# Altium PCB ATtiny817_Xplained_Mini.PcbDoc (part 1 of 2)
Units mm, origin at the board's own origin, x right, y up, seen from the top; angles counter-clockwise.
Board outline 60 x 75 mm, 4 copper layers (Top Layer, Ground Plane, Power Plane, Bottom Layer), stack 0.778 mm thick; 64 components, 81 nets, 498 pads, 125 vias.
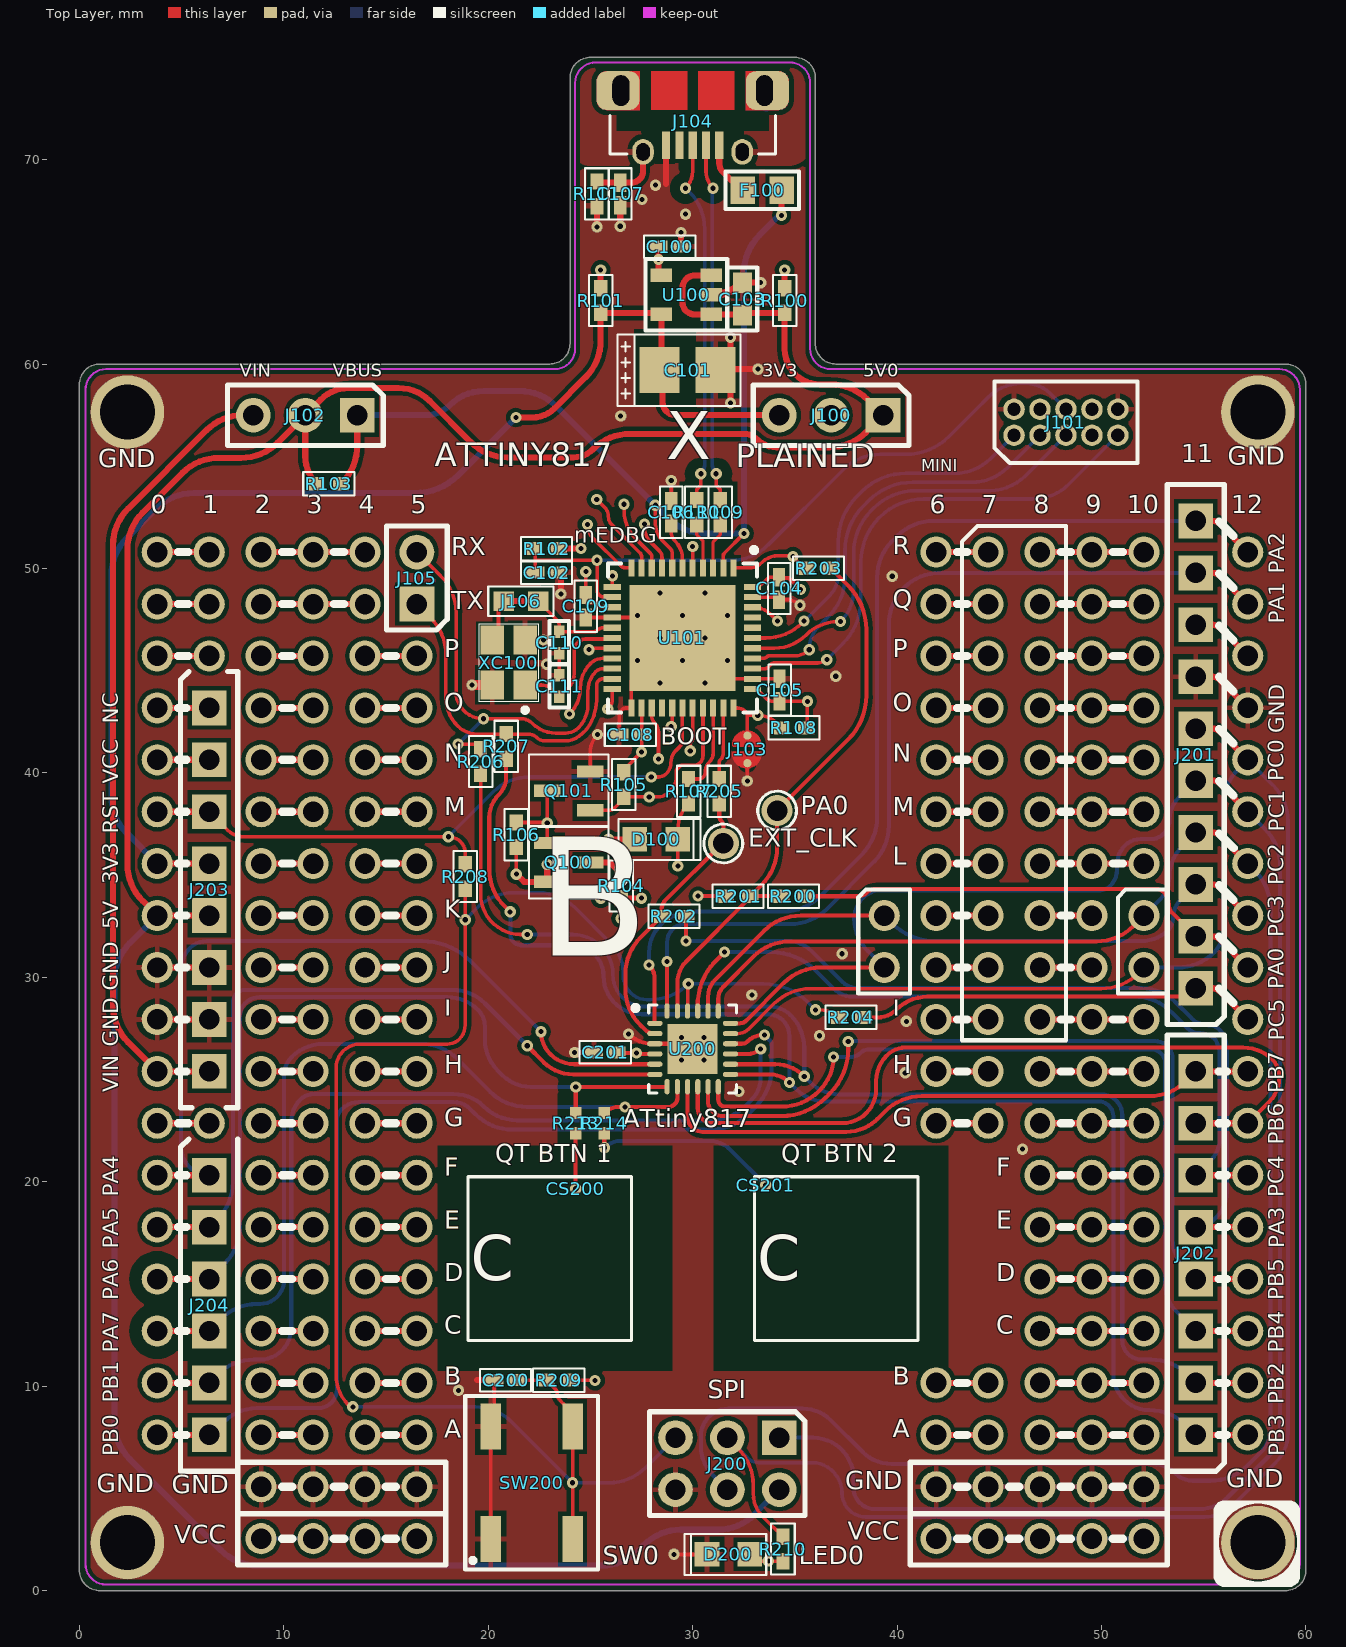
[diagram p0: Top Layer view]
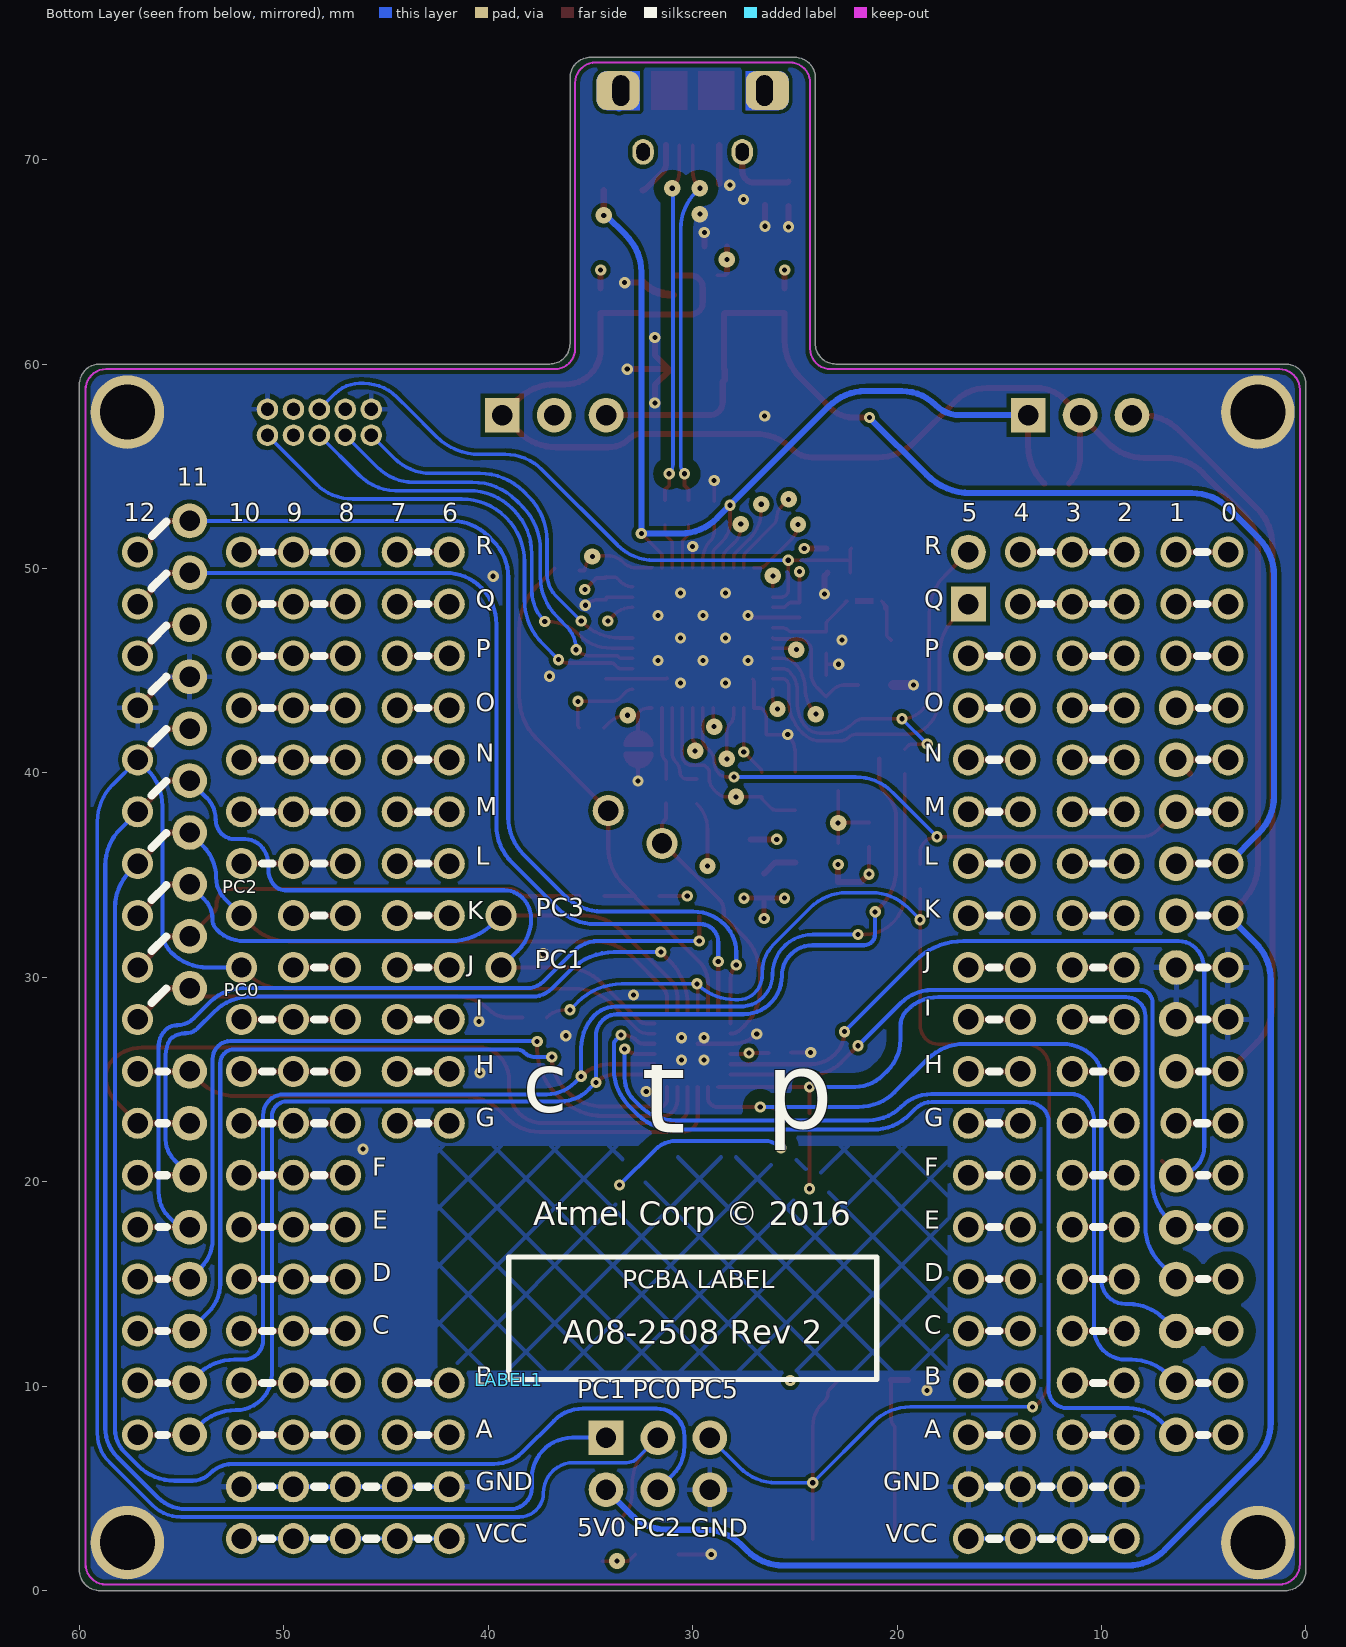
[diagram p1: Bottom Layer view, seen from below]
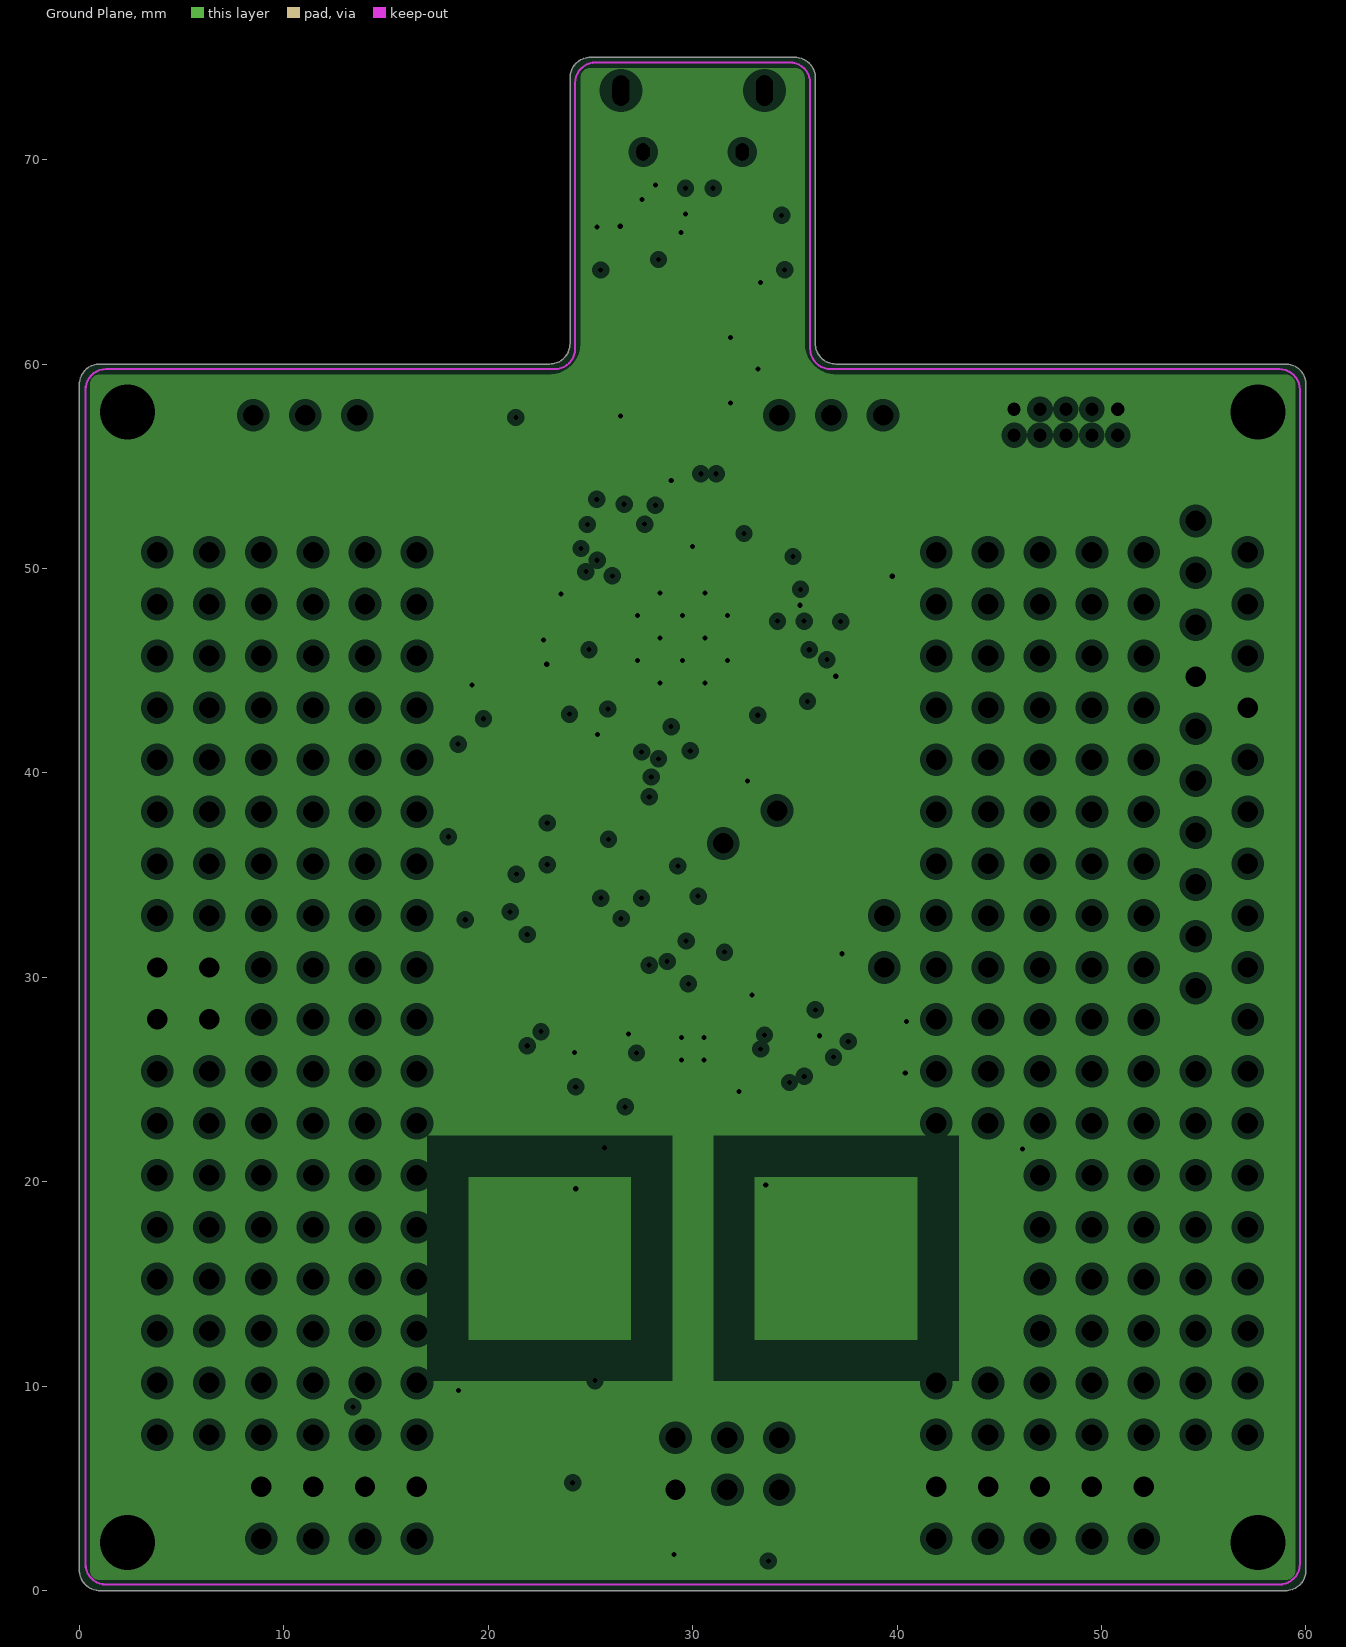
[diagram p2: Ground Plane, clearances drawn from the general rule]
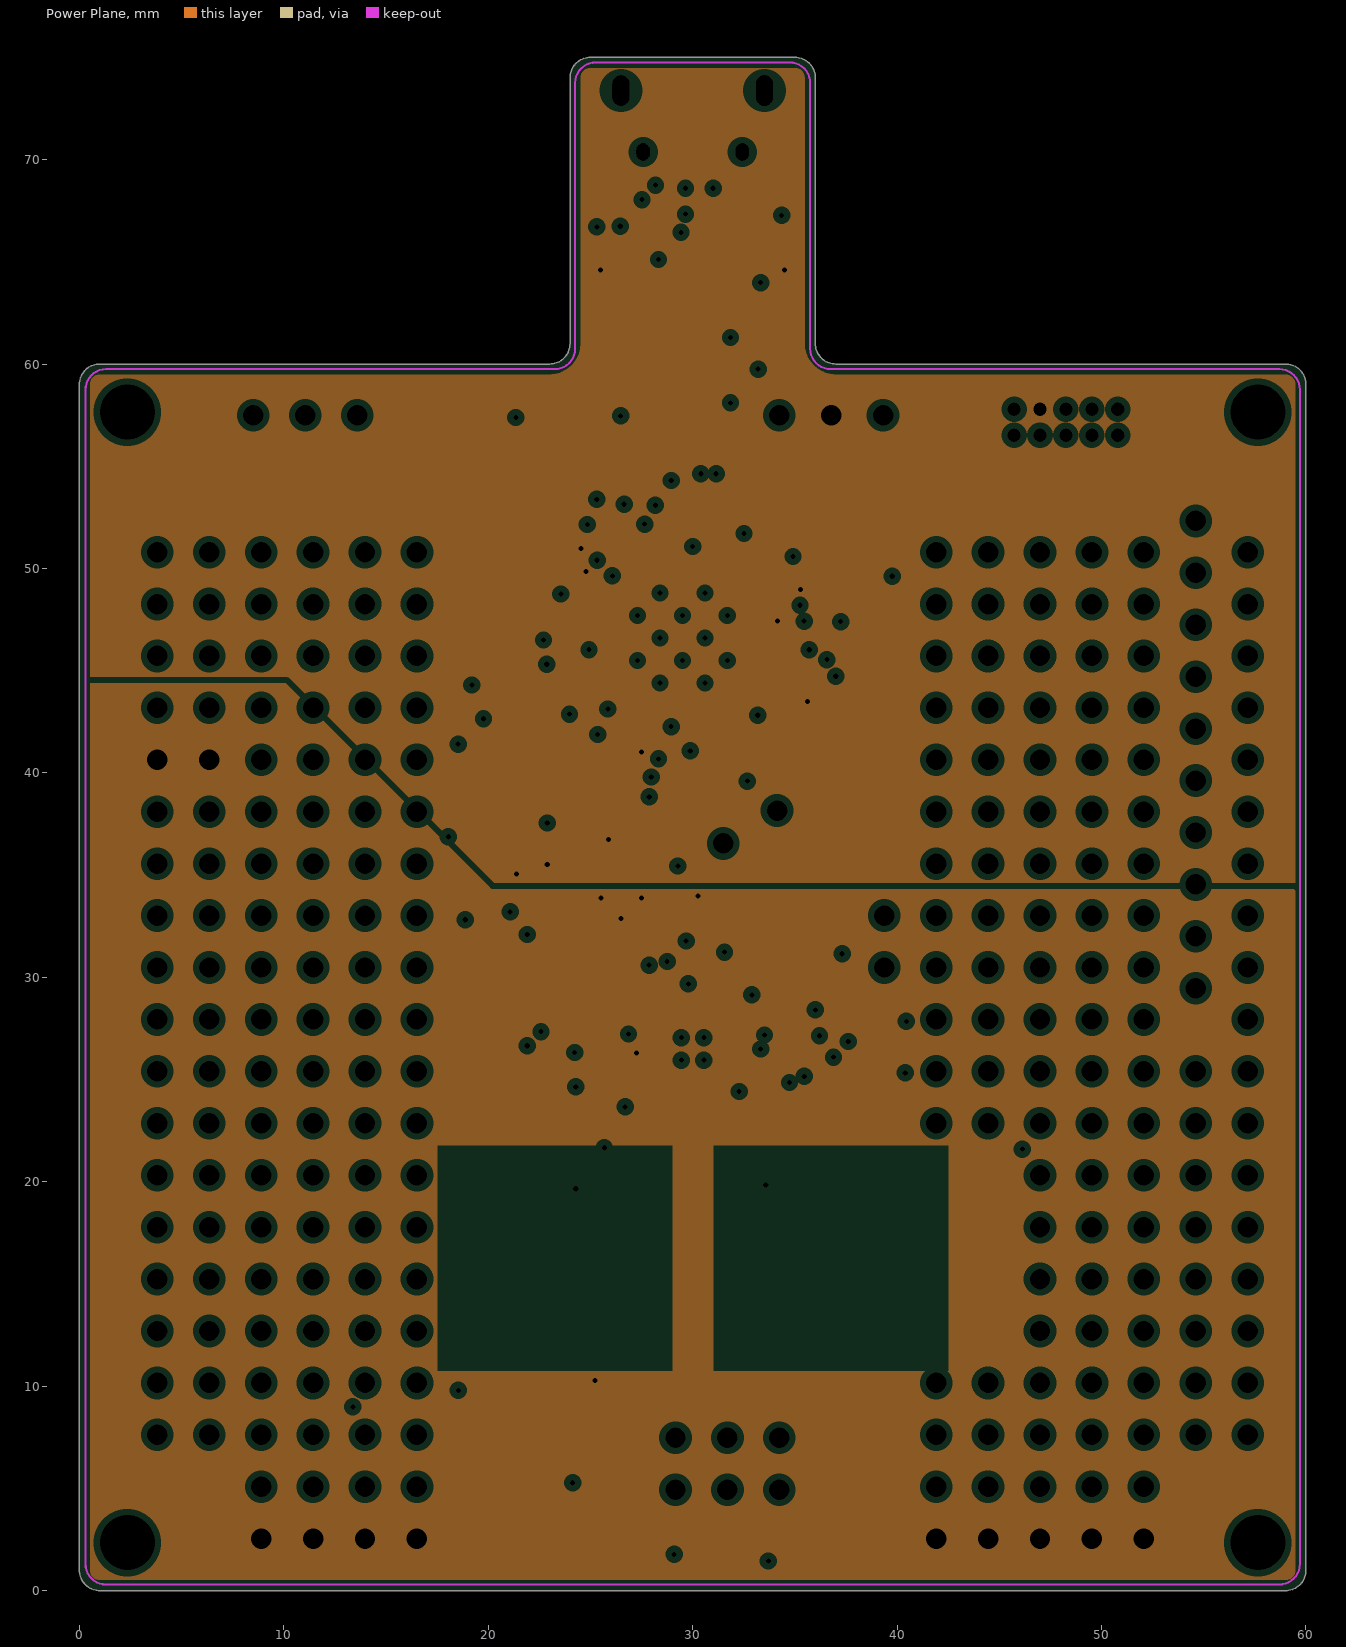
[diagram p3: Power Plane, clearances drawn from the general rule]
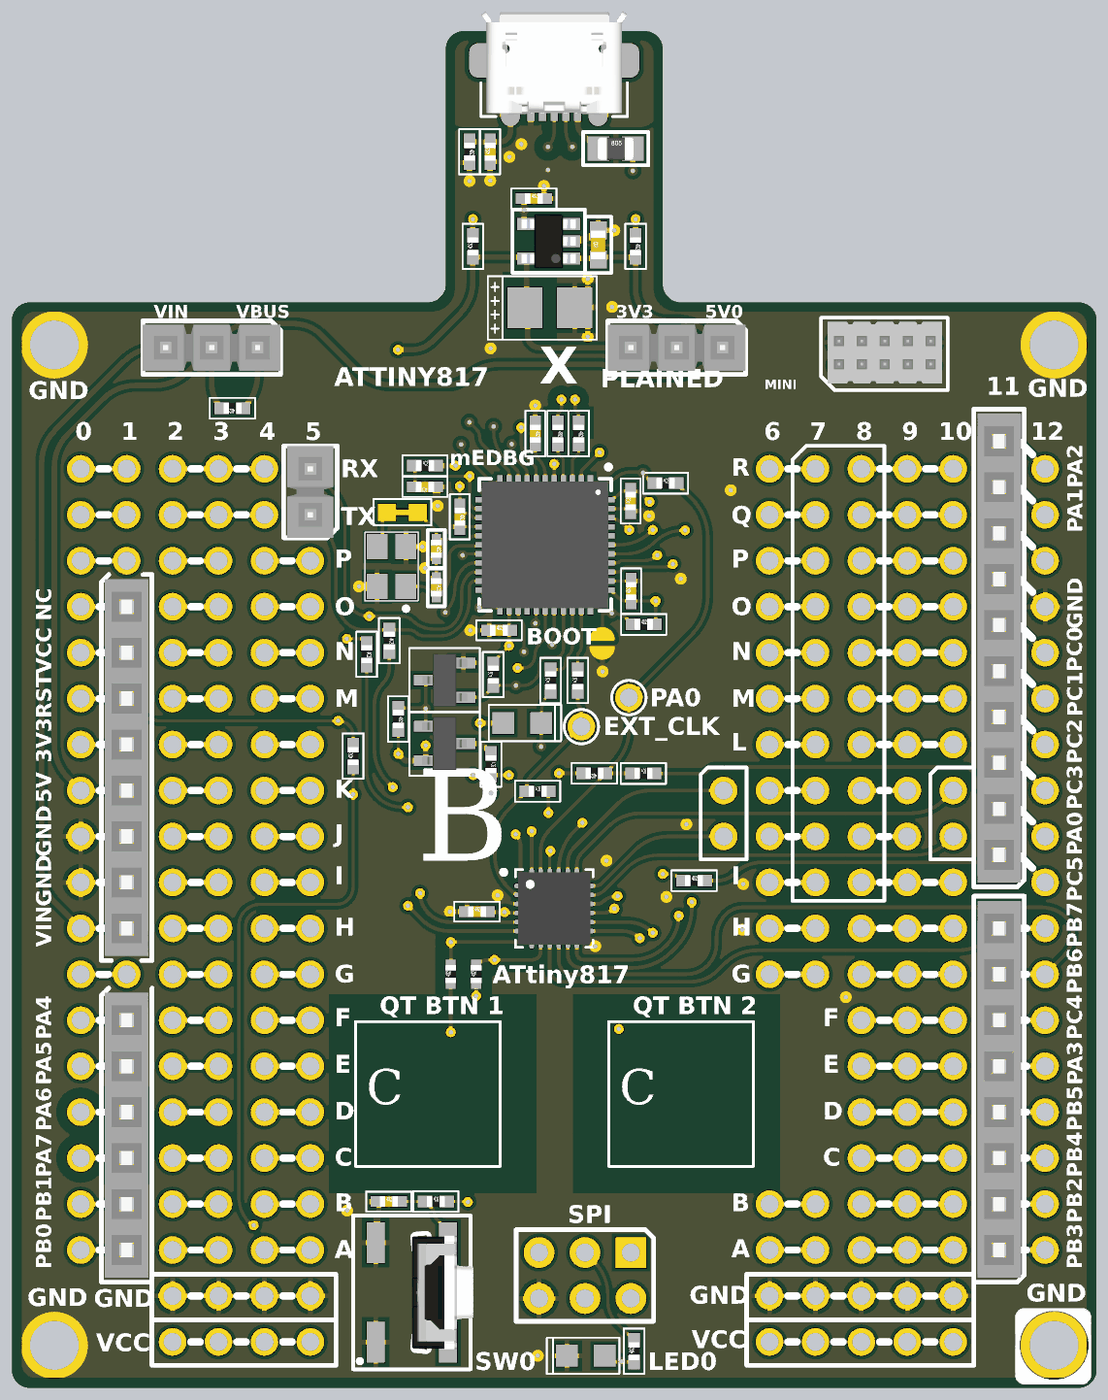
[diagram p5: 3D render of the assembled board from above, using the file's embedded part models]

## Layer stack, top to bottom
Top Solder: solder mask 0.0102, Solder Resist, Dk 3.5
Top Layer: signal copper 0.0356
Dielectric 1: core 0.254, Dk 4.2
Ground Plane: plane copper 0.036, net GND
Dielectric 4: prepreg 0.127, Dk 4.2
Power Plane: plane copper 0.0356, net (Multiple Nets)
Dielectric 3: core 0.254, Dk 4.2
Bottom Layer: signal copper 0.0356
Bottom Solder: solder mask 0.0102, Solder Resist, Dk 3.5

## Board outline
0,1 0,59 cw(c1,59) 1,60 23,60 ccw(c23,61) 24,61 24,74 cw(c25,74) 25,75 35,75 cw(c35,74) 36,74 36,61 ccw(c37,61) 37,60 59,60 cw(c59,59) 60,59 60,1 cw(c59,1) 59,0 1,0 cw(c1,1)

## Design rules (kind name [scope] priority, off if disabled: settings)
AcuteAngle [All] p1: minimum=7.50000000000000E+0001 checktracksonly=FALSE
AssemblyTestPointUsage "Schematic Assembly Testpoint Usage_21" [InNet('PA7_PTC3')] p1: valid=1
AssemblyTestPointUsage "Schematic Assembly Testpoint Usage_20" [InNet('PA6_PTC2')] p2: valid=1
AssemblyTestPointUsage "Schematic Assembly Testpoint Usage_17" [InNet('XTAL2')] p3: valid=1
AssemblyTestPointUsage "Schematic Assembly Testpoint Usage_16" [InNet('XTAL1')] p4: valid=1
AssemblyTestPointUsage "Schematic Assembly Testpoint Usage_15" [InNet('NetJ106_1')] p5: valid=1
AssemblyTestPointUsage "Schematic Assembly Testpoint Usage_1" [InNet('D_P')] p6: valid=1
AssemblyTestPointUsage "Schematic Assembly Testpoint Usage" [InNet('D_N')] p7: valid=1
AssemblyTestPointUsage [All] p8: allowmultiple=TRUE
AssemblyTestpoint [All] p1: testpointundercomponent=TRUE minsize=0.55 maxsize=2 preferedsize=0.8 minholesize=0 maxholesize=1 preferedholesize=0.25 testpointgrid=0.025 usegrid=FALSE gridtolerance=0 allowsidebottom=TRUE minspacing=1.27 compbodyclearance=0.127
Clearance Clearance_Touch [InNet('PA6_AIN06') OR InNet('PA6_PTC2') OR InNet('PA7_AIN07') OR InNet('PA7_PTC3') vs InPoly] p1: gap=0.6
Clearance Clearance_USB [InPoly vs InNet('USBD_P') OR InNet('USBD_N')] p2: gap=0.5
Clearance Clearance_Poly [InPoly] p3: gap=0.2
Clearance [All] p4: gap=0.15
DiffPairsRouting [All] p1: maxlimit=0.3 minlimit=0.15 mostfreqgap=0.2 toplayer_minwidth=0.15 toplayer_maxwidth=0.18 toplayer_prefwidth=0.15 bottomlayer_minwidth=0.15 bottomlayer_maxwidth=0.18 bottomlayer_prefwidth=0.15 maxuncoupledlength=20
FabricationTestPointUsage TestPointUsage [All] p1: valid=0 allowmultiple=TRUE
FabricationTestpoint Testpoint [All] p1: side=2 testpointundercomponent=TRUE minsize=0.55 maxsize=2 preferedsize=0.8 minholesize=0 maxholesize=1 preferedholesize=0.25 testpointgrid=0 allowsidebottom=TRUE usegrid=FALSE gridtolerance=0 minspacing=1.27 compbodyclearance=0.127
HoleSize [All] p1: absolutevalues=TRUE maxlimit=10 minlimit=0.25 maxpercent=80.000 minpercent=20.000
HoleToHoleClearance [All] p1: gap=0.45 allowstackedmicrovias=TRUE
MinimumAnnularRing MinimumAnnularRing_JTAG [InComponent('J100')] p1: minimumring=0.075
MinimumAnnularRing [All] p2: minimumring=0.15
MinimumSolderMaskSliver [All] p1: minsoldermaskwidth=0.05
NetAntennae [Not IsTestpoint] p1: netantennaetolerance=0
PlaneClearance [All] p1: clearance=0.3
PlaneConnect PlaneConnect_VIA [IsVia OR HasPad('Free-666')] p1: planeconnectstyle=Direct reliefexpansion=0.508 reliefentries=4 reliefconductorwidth=0.254 reliefairgap=0.254
PlaneConnect [All] p2: planeconnectstyle=Relief reliefexpansion=0.508 reliefentries=4 reliefconductorwidth=0.254 reliefairgap=0.254
PolygonConnect PolygonConnect_VIA [IsVia OR HasPad('Free-666')] p1: connectstyle=Direct reliefconductorwidth=0.254 reliefentries=4 polygonreliefangle="90 Angle" airgapwidth=0.254
PolygonConnect [All] p2: connectstyle=Relief reliefconductorwidth=0.254 reliefentries=4 polygonreliefangle="90 Angle" airgapwidth=0.254
RoutingVias [All] p1: holewidth=0.25 width=0.55 viastyle="Through Hole" minholewidth=0.25 minwidth=0.55 maxholewidth=0.5 maxwidth=1
SMDNeckDown [All] p1: percent=90.000
SilkToSilkClearance SilkToSilkClearance_Text [IsText] p1: silktosilkclearance=0
SilkToSilkClearance [All] p2: silktosilkclearance=0.1
SilkToSolderMaskClearance SilkscreenOverComponentPads [IsPad] p1: minsilkscreentomaskgap=0.05 clearancetoexposedcopper=TRUE
SolderMaskExpansion SolderMaskTenting [IsVia AND NOT (IsFabTestpoint OR IsAssyTestpoint)] p1: expansion=-1
SolderMaskExpansion [All] p2: expansion=0.05
ViasUnderSMD [All] p1: allowed=FALSE
Width [All] p1: maxlimit=10 minlimit=0.175 preferedwidth=0.175
17 further rules are at their usual default settings.

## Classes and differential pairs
component class ATtiny817_Xplained_Mini_TopLevel: FW1 LABEL1 PCB1 PCBADOC1 TEST2 TESTDOC1
component class "Target device": C200 C201 CS200 CS201 D200 J200 J201 J202 J203 J204 R200 R201 R202 R203 R204 R205 R206 R207 R208 R209 R210 R213 R214 SW200 U200
component class Programmer/Debug: C100 C101 C102 C103 C104 C105 C106 C107 C108 C109 C110 C111 D100 F100 J100 J101 J102 J103 J104 J105 J106 Q100 Q101 Q102 R100 R101 R102 R103 R104 R105 R106 R107 R108 R109 R110 R111 U100 U101 XC100
differential pair D: +D_P -D_N
differential pair USBD: +USBD_P -USBD_N

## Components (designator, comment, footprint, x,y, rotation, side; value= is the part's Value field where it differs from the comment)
C100 "" AP1-00001 28.88,65.746 r0 top
C101 "" AP1-00008 29.75,59.7 r0 top
C102 "" AP1-00001 22.85,49.8 r180 top
C103 "Farnell no.: 1833806" AP1-00002 32.436,63.181 r90 top
C104 "" AP1-00001 34.225,49.025 r90 top
C105 "" AP1-00001 34.25,44.05 r90 top
C106 "" AP1-00001 28.95,52.75 r270 top
C107 "" AP1-00001 26.458,68.326 r90 top
C108 "" AP1-00001 26.95,41.875 r0 top
C109 "" AP1-00001 24.775,48.15 r270 top
C110 "" AP1-00038 23.475,45.85 r180 top
C111 "" AP1-00038 23.475,43.725 r180 top
C200 "" AP1-00001 20.85,10.3 r0 top
C201 "" AP1-00001 25.725,26.325 r0 top
CS200 "QTouch Button" ?#1 23,16.2 r0 top
CS201 "QTouch Button" ?#2 37,16.2 r0 top
D100 "" AP4-00013 28.225,36.75 r180 top
D200 "" AP4-00013 31.75,1.775 r0 top
F100 "Farnell no: 1861197" AP2-00002 33.4,68.5 r0 top
J100 "" AP8-00745 36.775,57.5 r180 top locked
J101 "" AP8-00257 48.26,57.15 r0 top locked
J102 "" AP8-00745 11.05,57.5 r180 top locked
J103 "" AP9-00034 32.675,41.15 r90 top locked
J104 "2,000 pieces per reel" AP8-00851 30,73.375 r180 top locked
J105 "" AP8-00733 16.51,49.53 r90 top locked
J106 "" AP9-00044 21.6,48.4 r0 top net-tie
J200 "" AP8-00182 31.7,6.21 r180 top locked
J201 "" AP8-00822 54.61,40.894 r90 top locked
J202 "" AP8-00823#1 54.61,16.51 r90 top locked
J203 "" AP8-00823#2 6.35,34.29 r270 top locked
J204 "" AP8-00824 6.35,13.97 r270 top locked
LABEL1 "" AP8-00317 39,10.325 r180 bottom
Q100 "" AP5-00002 23.935,35.62 r0 top
Q101 "" AP5-00002 23.935,39.12 r180 top
R100 "" AP2-00000 34.5,63.1 r270 top
R101 "" AP2-00000 25.5,63.1 r90 top
R102 "" AP2-00000 22.85,50.975 r0 top
R103 "" AP2-00000 12.2,54.15 r180 top
R104 "" AP2-00000 26.502,34.473 r270 top
R105 "" AP2-00000 26.625,39.425 r90 top
R106 "" AP2-00000 21.375,36.975 r270 top
R107 "" AP2-00000 29.8,39.1 r90 top
R108 "" AP2-00000 34.95,42.2 r0 top
R109 "" AP2-00000 31.35,52.75 r270 top
R110 "" AP2-00000 30.2,52.75 r270 top
R111 "" AP2-00000 25.315,68.326 r270 top
R200 "" AP2-00000 34.929,33.964 r0 top
R201 "" AP2-00000 32.219,33.972 r180 top
R202 "" AP2-00000 29.079,32.978 r0 top
R203 "" AP2-00000 36.158,50.008 r0 top
R204 "" AP2-00000 37.738,28.036 r0 top
R205 "" AP2-00000 31.3,39.1 r90 top
R206 "" AP2-00000 19.625,40.55 r270 top
R207 "" AP2-00000 20.875,41.3 r270 top
R208 "" AP2-00000 18.875,34.925 r90 top
R209 "" AP2-00000 23.45,10.3 r0 top
R210 "" AP2-00000 34.417,2.032 r90 top
R213 "" AP2-00011 24.275,22.868 r90 top
R214 "" AP2-00011 25.675,22.868 r90 top
SW200 "" AP8-00137 22.125,5.275 r90 top
U100 "" AP6-00087 29.693,63.384 r180 top
U101 "" AP6-00375 29.5,46.6 r270 top locked
U200 "ATtiny807" AP6-00459 30,26.5 r0 top locked
XC100 "" AP7-00061 21,45.4 r90 top

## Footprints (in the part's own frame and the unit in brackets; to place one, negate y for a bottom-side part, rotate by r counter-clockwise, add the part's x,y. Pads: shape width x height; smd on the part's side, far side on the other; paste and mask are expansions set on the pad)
AP1-00001 [mm] "Standard 0402 SMD capacitor footprint"
  rect 0.9x0.6 smd: 1(-0.55,0) 2(0.55,0)
  silkscreen extent -1.25,-0.55 1.25,0.55, body extent -0.5,-0.3 0.5,0.3, height 0.2
AP1-00002 [mm]
  rect 1x0.95 smd: 1(-0.8,0) 2(0.8,0)
  silkscreen extent -1.55,-0.72 1.55,0.72, body extent -0.8,-0.4 0.8,0.4, height 0.3
AP1-00008 [mm]
  rect 1.95x2.25 smd: 1(-1.375,0) 2(1.375,0)
  silkscreen extent -3.42,-1.75 2.6,1.75, body extent -1.9,-1.5 1.9,1.5, height 2.11
AP1-00038 [mm] "Generic pad 0402, spacing 0.45mm"
  rect 0.5x0.6 smd: 1(0,0) 2(0,-1.05)
  silkscreen extent -0.48,-1.58 0.48,0.53, body extent -0.3,-1.02 0.3,-0.03, height 0.2
AP2-00000 [mm] "Standard 0402 SMD resistor footprint"
  rect 0.8x0.65 smd: 1(-0.6,0) 2(0.6,0)
  silkscreen extent -1.25,-0.58 1.25,0.58, body extent -0.5,-0.3 0.5,0.3, height 0.2
AP2-00002 [mm]
  rect 1.2x1.35 smd: 1(-0.95,0) 2(0.95,0)
  silkscreen extent -1.8,-0.92 1.8,0.92, body extent -1,-0.62 1,0.63, height 0.78
AP2-00011 [mm] "Chip Resistor, 2-Leads, Body 1,0x0,5mm, IPC High Density"
  rect 0.6x0.55 smd: 1(-0.5,0) 2(0.5,0)
  body extent -0.5,-0.3 0.5,0.3, height 0.2
AP4-00013 [mm] "0805 diode footprint"
  rect 1.2x1.2 smd: 1(-1.05,0) 2(1.05,0)
  silkscreen extent -2.16,-1 1.85,1, body extent -1,-0.63 1,0.63, height 1.1
AP5-00002 [mm] "SOT-23 Package"
  rect 1.3x0.6 smd: 1(-1.05,0.95) 2(-1.05,-0.95) 3(1.05,0)
  silkscreen extent -1.95,-1.78 1.95,1.78, body extent -1.25,-1.46 1.23,1.46, height 1
AP6-00087 [mm]
  rect 1.05x0.65 smd: 1(-1.225,0.953) 2(-1.225,0) 3(-1.225,-0.953) 4(1.225,-0.953) 5(1.225,0.953)
  silkscreen extent -2,-1.75 2,1.75, body extent -1.5,-1.5 1.5,1.5, height 1.3
AP6-00375 [mm] "QFN, 44-Leads, Body 7,00x7,00mm, Pitch 0,50mm, Thermal Pad 5,20x5,20mm, IPC Medium Density"
  rect 0.85x0.3 smd: 1(-3.425,2.5) 2(-3.425,2) 3(-3.425,1.5) 4(-3.425,1) 5(-3.425,0.5) 6(-3.425,0) 7(-3.425,-0.5) 8(-3.425,-1) 9(-3.425,-1.5) 10(-3.425,-2) 11(-3.425,-2.5) 23(3.425,-2.5) 24(3.425,-2) 25(3.425,-1.5) 26(3.425,-1) 27(3.425,-0.5) 28(3.425,0) 29(3.425,0.5) 30(3.425,1) 31(3.425,1.5) 32(3.425,2) 33(3.425,2.5)
  rect 0.3x0.85 smd: 12(-2.5,-3.425) 13(-2,-3.425) 14(-1.5,-3.425) 15(-1,-3.425) 16(-0.5,-3.425) 17(0,-3.425) 18(0.5,-3.425) 19(1,-3.425) 20(1.5,-3.425) 21(2,-3.425) 22(2.5,-3.425) 34(2.5,3.425) 35(2,3.425) 36(1.5,3.425) 37(1,3.425) 38(0.5,3.425) 39(0,3.425) 40(-0.5,3.425) 41(-1,3.425) 42(-1.5,3.425) 43(-2,3.425) 44(-2.5,3.425)
  rect 5.2x5.2 smd: 45(0,0)
  silkscreen extent -4.42,-3.65 3.65,3.65, body extent -3.5,-3.5 3.5,3.5, height 0.89
AP6-00459 [mm] "QFN, 24-Leads, Body 4,00x4,00mm, Pitch 0,50mm, Thermal Pad 2,45x2,45mm, IPC High Density"
  oval 0.75x0.25 smd: 1(-1.85,1.25) 2(-1.85,0.75) 3(-1.85,0.25) 4(-1.85,-0.25) 5(-1.85,-0.75) 6(-1.85,-1.25) 13(1.85,-1.25) 14(1.85,-0.75) 15(1.85,-0.25) 16(1.85,0.25) 17(1.85,0.75) 18(1.85,1.25)
  oval 0.25x0.75 smd: 7(-1.25,-1.85) 8(-0.75,-1.85) 9(-0.25,-1.85) 10(0.25,-1.85) 11(0.75,-1.85) 12(1.25,-1.85) 19(1.25,1.85) 20(0.75,1.85) 21(0.25,1.85) 22(-0.25,1.85) 23(-0.75,1.85) 24(-1.25,1.85)
  rect 2.45x2.45 smd: 25(0,0)
  silkscreen extent -2.92,-2.15 2.15,2.15, body extent -2,-2 2,2, height 0.9
AP7-00061 [mm] "TSX-3225"
  rect 1.4x1.15 smd: 1(-1.1,-0.8) 2(1.1,-0.8) 3(1.1,0.8) 4(-1.1,0.8)
  silkscreen extent -2.43,-1.48 1.9,1.48, body extent -1.6,-1.25 1.6,1.25, height 0.6
AP8-00137 [mm]
  rect 2.25x1 smd: 1(-2.75,2) 2(2.75,2) 3(-2.75,-2) 4(2.75,-2)
  silkscreen extent -4.25,-3.25 4.25,3.25, body extent -3.4,-3.21 3.4,3.22, height 3.47
AP8-00182 [mm] "Pin-in-Paste, Throughhole pin-header (2x3 array). Pitch 2.54 mm"
  rect 1.7x1.7 / inner round 1.7 / far side rect 1.7x1.7 hole 1: 1(-2.54,-1.27)
  rect 0x0 on Top Paste paste-2: 1(-2.54,-1.27) 2(-2.54,1.27) 3(0,-1.27) 4(0,1.27) 5(2.54,-1.27) 6(2.54,1.27)
  round 1.7 hole 1: 2(-2.54,1.27) 3(0,-1.27) 4(0,1.27) 5(2.54,-1.27) 6(2.54,1.27)
  silkscreen extent -3.8,-2.54 3.81,2.54, body extent -3.81,-2.54 3.81,2.54, height 8
AP8-00257 [mm]
  round 1.05 hole 0.65: 1(-2.54,-0.635) 2(-2.54,0.635) 3(-1.27,-0.635) 4(-1.27,0.635) 5(0,-0.635) 6(0,0.635) 7(1.27,-0.635) 8(1.27,0.635) 9(2.54,-0.635) 10(2.54,0.635)
  silkscreen extent -3.5,-2 3.5,2, body extent -3.15,-1.64 3.2,1.79, height 3.88
AP8-00317 [mm] "Placement area for 18x6mm sticker"
  silkscreen extent 0,0 18,6
AP8-00733 [mm] "Pin header 1x2 Pin in Paste"
  rect 1.7x1.7 / inner round 1.7 / far side rect 1.7x1.7 hole 1: 1(-1.27,0)
  rect 0x0 on Top Paste paste-2: 1(-1.27,0)
  round 1.7 hole 1: 2(1.27,0)
  rect 0x0 on Top Paste paste+2: 2(1.27,0)
  silkscreen extent -2.54,-1.48 2.54,1.48, body extent -2.54,-1.27 2.54,1.27, height 8.38
AP8-00745 [mm] "THM Pin-header 1x3 100mil pitch, 1mm hole"
  rect 1.7x1.7 / inner round 1.7 / far side rect 1.7x1.7 hole 1: 1(-2.54,0)
  round 1.7 hole 1: 2(0,0) 3(2.54,0)
  silkscreen extent -3.81,-1.48 3.81,1.48, body extent -3.81,-1.27 3.81,1.27, height 8.38
AP8-00822 [mm]
  rect 1.7x1.7 / inner round 1.7 / far side round 1.7 hole 1: 1(-11.43,0) 2(-8.89,0) 3(-6.35,0) 4(-3.81,0) 5(-1.27,0) 6(1.27,0) 7(3.81,0) 8(6.35,0) 9(8.89,0)
  rect 0x0 on Top Paste paste-2: 1(-11.43,0) 2(-8.89,0) 3(-6.35,0) 4(-3.81,0) 5(-1.27,0) 6(1.27,0) 7(3.81,0) 8(6.35,0) 9(8.89,0)
  rect 1.7x1.7 / inner round 1.7 / far side round 1.7 hole 1 paste+2: 10(11.43,0)
  rect 0x0 on Top Paste paste+2: 10(11.43,0)
  silkscreen extent -13.21,-1.4 13.21,1.4, body extent -12.95,-1.21 12.95,1.21, height 8.51
AP8-00823#1 [mm]
  rect 1.7x1.7 / inner round 1.7 / far side round 1.7 hole 1: 1(-8.89,0) 2(-6.35,0) 3(-3.81,0) 4(-1.27,0) 5(1.27,0) 6(3.81,0) 7(6.35,0) 8(8.89,0)
  silkscreen extent -10.67,-1.4 10.67,1.4, body extent -10.41,-1.21 10.41,1.21, height 8.51
AP8-00823#2 [mm]
  rect 1.7x1.7 / inner round 1.7 / far side round 1.7 hole 1: 1(-8.89,0) 2(-6.35,0) 3(-3.81,0) 4(-1.27,0) 5(1.27,0) 6(3.81,0) 7(6.35,0) 8(8.89,0)
  rect 0x0 on Top Paste paste-2: 1(-8.89,0) 2(-6.35,0) 3(-3.81,0) 4(-1.27,0) 5(1.27,0) 6(3.81,0) 7(6.35,0) 8(8.89,0)
  silkscreen extent -10.67,-1.4 10.67,1.4, body extent -10.41,-1.21 10.41,1.21, height 8.51
AP8-00824 [mm]
  rect 1.7x1.7 / inner round 1.7 / far side round 1.7 hole 1: 1(-6.35,0) 2(-3.81,0) 3(-1.27,0) 4(1.27,0) 5(3.81,0) 6(6.35,0)
  rect 0x0 on Top Paste paste-2: 1(-6.35,0) 2(-3.81,0) 3(-1.27,0) 4(1.27,0) 5(3.81,0) 6(6.35,0)
  silkscreen extent -8.13,-1.4 8.13,1.4, body extent -7.87,-1.21 7.87,1.21, height 8.51
AP8-00851 [mm] "Hirose, ZX Series, USB Micro-B Recept-RA"
  rect 0.4x1.35 smd: 1(-1.3,2.675) 2(-0.65,2.675) 3(0,2.675) 4(0.65,2.675) 5(1.3,2.675)
  rrect52% 2.1x1.9 on Top Paste: 6(-3.6,0) 7(3.6,0)
  rrect52% 2.1x1.9 hole 0.825 slot 1.5 at 90 deg copper offset -0.138,0: 6(-3.512,0)
  rrect52% 2.1x1.9 hole 0.825 slot 1.5 at 90 deg copper offset 0.138,0: 7(3.512,0)
  rrect100% 1.05x1.25 hole 0.65 slot 0.85 at 90 deg: 8(-2.425,3) 9(2.425,3)
  rrect100% 1.05x1.25 on Top Paste: 8(-2.425,3) 9(2.425,3)
  Top Layer region: 0.249,-0.95 2.049,-0.95 2.049,0.95 0.249,0.95
  Top Layer region: -2.049,-0.95 -0.249,-0.95 -0.249,0.95 -2.049,0.95
  Top Layer region: 2.6,-0.95 4.2,-0.95 4.294,-0.941 4.381,-0.915 4.434,-0.891 4.48,-0.862 4.52,-0.832 4.565,-0.791 4.596,-0.753 4.622,-0.716 4.647,-0.673 4.66,-0.64 4.676,-0.6 4.688,-0.55 4.696,-0.505 4.7,-0.45 4.7,0.45 4.696,0.503 4.689,0.548 4.677,0.599 4.661,0.641 4.641,0.683 4.617,0.724 4.589,0.761 4.56,0.797 4.521,0.831 4.483,0.86 4.439,0.888 4.397,0.908 4.354,0.924 4.301,0.939 4.248,0.946 4.2,0.95 2.6,0.95
  Top Layer region: -2.6,0.95 -4.2,0.95 -4.294,0.941 -4.381,0.915 -4.434,0.891 -4.48,0.862 -4.52,0.832 -4.565,0.791 -4.596,0.753 -4.622,0.716 -4.647,0.673 -4.66,0.64 -4.676,0.6 -4.688,0.55 -4.696,0.505 -4.7,0.45 -4.7,-0.45 -4.696,-0.503 -4.689,-0.548 -4.677,-0.599 -4.661,-0.641 -4.641,-0.683 -4.617,-0.724 -4.589,-0.761 -4.56,-0.797 -4.521,-0.831 -4.483,-0.86 -4.439,-0.888 -4.397,-0.908 -4.354,-0.924 -4.301,-0.939 -4.248,-0.946 -4.2,-0.95 -2.6,-0.95
  Top Layer pour cut-out: -3.75,2 3.75,2 3.75,-1.45 -3.75,-1.45
  Bottom Layer region: -2.6,0.95 -4.2,0.95 -4.294,0.941 -4.381,0.915 -4.434,0.891 -4.48,0.862 -4.52,0.832 -4.565,0.791 -4.596,0.753 -4.622,0.716 -4.647,0.673 -4.66,0.64 -4.676,0.6 -4.688,0.55 -4.696,0.505 -4.7,0.45 -4.7,-0.45 -4.696,-0.503 -4.689,-0.548 -4.677,-0.599 -4.661,-0.641 -4.641,-0.683 -4.617,-0.724 -4.589,-0.761 -4.56,-0.797 -4.521,-0.831 -4.483,-0.86 -4.439,-0.888 -4.397,-0.908 -4.354,-0.924 -4.301,-0.939 -4.248,-0.946 -4.2,-0.95 -2.6,-0.95
  Bottom Layer region: 2.6,-0.95 4.2,-0.95 4.294,-0.941 4.381,-0.915 4.434,-0.891 4.48,-0.862 4.52,-0.832 4.565,-0.791 4.596,-0.753 4.622,-0.716 4.647,-0.673 4.66,-0.64 4.676,-0.6 4.688,-0.55 4.696,-0.505 4.7,-0.45 4.7,0.45 4.696,0.503 4.689,0.548 4.677,0.599 4.661,0.641 4.641,0.683 4.617,0.724 4.589,0.761 4.56,0.797 4.521,0.831 4.483,0.86 4.439,0.888 4.397,0.908 4.354,0.924 4.301,0.939 4.248,0.946 4.2,0.95 2.6,0.95
  silkscreen extent -4.05,1.22 4.05,3.1, body extent -4.05,-2.7 4.05,3.1, height 2.75
AP9-00034 [mm] "PCB implemented strap, open"
  round 0.4 smd paste-0.4 mask-0.4: 1(-0.675,0) 2(0.675,0)
  Top Layer region: 0.2,0.675 0.482,0.611 0.708,0.43 0.834,0.17 0.834,-0.12 0.708,-0.38 0.482,-0.561 0.2,-0.625 0.2,-0.625
  Top Layer region: -0.2,-0.625 -0.482,-0.561 -0.708,-0.38 -0.834,-0.12 -0.834,0.17 -0.708,0.43 -0.482,0.611 -0.2,0.675 -0.2,0.675
  Top Layer lines w0.175: -0.2,0.675 ccw(c-0.2,0.025) -0.85,0 ccw(c-0.2,0.025) -0.2,-0.625 -0.2,0.675 ; 0.2,0.675 cw(c0.2,0.025) 0.85,0 cw(c0.2,0.025) 0.2,-0.625 0.2,0.675
AP9-00044 [mm]
  rect 1x0.95 smd paste-1: 1(-0.85,0) 2(0.85,0)
  Top Layer region: -0.45,-0.15 0.45,-0.15 0.45,0.15 -0.45,0.15
  silkscreen extent -1.6,-0.72 1.6,0.72, body extent -0.8,-0.4 0.8,0.4, height 0.3
?#1 [mm]
  round 0.55 smd paste-1 mask-1: 1(1.281,3.458)
  Ground Plane region: -5.975,-3.956 -5.975,6.042 6.012,6.042 6.012,-5.946 4.005,-5.946 -5.975,-5.946 -5.975,-3.956 4.005,-3.956 4.005,4.053 -3.986,4.053 -3.986,-3.956
?#2 [mm]
  round 0.55 smd paste-1 mask-1: 1(-3.425,3.638)
  Ground Plane region: -5.975,-3.956 -5.975,6.042 6.012,6.042 6.012,-5.946 4.005,-5.946 -5.975,-5.946 -5.975,-3.956 4.005,-3.956 4.005,4.053 -3.986,4.053 -3.986,-3.956

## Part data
C100: library part A01-0050, "Ceramic capacitor, SMD 0402, X7R, 25V, +/-10%"
C101: library part A01-0292, "SMD tantalum capacitor, precision molded chip, ESR=0,5"
C102 C104 C105 C108 C109 C200 C201: library part A01-0246, "Ceramic capacitor, SMD 0402, X7R, 16V, +/-10%"
C103: library part A01-0502, "Ceramic capacitor, SMD 0603, X5R, 10V, ±10 %"
C106: library part A01-0286, "Ceramic capacitor, SMD 0402, X5R, 6.3V, +/-10% (de26942)"
C107: library part A01-0046, "Ceramic capacitor, SMD 0402, X7R, 25V, +/-10% (de35287)"
C110 C111: library part A01-0355, "Ceramic capacitor, SMD 0402, NP0, 50V, +/-5% (de19819)"
CS200 CS201: library part QTouchButton
D100: library part A10-0018, "LED, Green, Wave length=575nm, SMD 0805, ±70°"
D200: library part A10-0019, "LED, Yellow, Wave length=591nm, SMD 0805, ±70°"
F100: library part A02-0622, "Resetable PTC fuse, Ih = 0.5A, It = 1.0A, 0805 package"
J100 J102: library part A08-1799, "1x3 pin header, 2.54mm pitch, Pin-in-Paste THM, 1mm hole"
J101: library part A08-0385, "2x5 pin header, 1.27mm pitch, THM"
J103: library part A09-0483, "Default open SMD strap"
J104: library part A08-2092, "Micro USB B Connector, Standard SMT + DIP"
J105: library part A08-1754, "1x2 pin header, 2.54mm pitch, Pin-in-Paste THM"
J106: library part A09-0783, "Default closed SMD strap, 0603 size"
J200: library part A08-0538, "2x3 pin header, 2.54 mm pitch, THM"
J201: library part A08-2026, "1x10 receptacle pin header, low insertion force, 2.54mm pitch THM, Pin in Paste"
J202 J203: library part A08-2025, "1x8 receptacle pin header, low insertion force, 2.54mm pitch THM, Pin in Paste"
J204: library part A08-2024, "1x6 receptacle pin header, low insertion force, 2.54mm pitch THM"
LABEL1: library part A09-0611, "PCBA identification label PP Top White Gloss"
Q100: library part A05-0087, "P-ch. MOSFET. -30V, -3.7A continuous,RDS(ON)=0.05Ohm@VGS=-4,5V, RDS(ON)=0.08Ohm@VGS=-2.5V"
Q101: library part A05-0085, "N-Channel MOSFET. 60V, 0.300A continuous, 1.2A Peak. RDS(ON) = 3.8Ohm@VGS=4.5V, VGS(th)<2.5V"
R100 R101 R103 R104 R200 R202 R203 R204 R208: library part A02-0163, "RES 0.0 OHM 1/16W 0402 SMD"
R102 R105 R106 R108 R209: library part A02-0260, "Thick film resistor, SMD 0402, 1/16W, 1%"
R107: library part A02-0208, "Thick film resistor, SMD 0402, 1/16W, 1%"
R109 R110: library part A02-0172, "Thick film resistor, SMD 0402, 1/16W, 1% (de23607)"
R111: library part A02-0284, "Thick film resistor, SMD 0402, 1/16W, 1%"
R201: library part A02-0224, "Thick film resistor, SMD 0402, 1/16W, 1%"
R205: library part A02-0200, "Thick film resistor, SMD 0402, 1/16W, 1%"
R206 R207 R210 R213 R214: library part A02-0212, "Thick film resistor, SMD 0402, 1/16W, 1%"
SW200: library part A08-0790, "6.2x6.2 mm SMD tact switch, same as A08-0091 but less force is needed"
U100: library part A06-1099, "LDO 3.3V 150mA SOT23-5 1.5% (cer. cap)"
U101: library part A06-0305, "ATmega32U4 QFN package"
U200: library part A06-1373, "Atmel 8-bit RISC MCU"
XC100: library part A07-0078, "16MHz uXtal, 3.2 x 2.5 mm SMD, CL=9pF, 15PPM, ESR=80ohm(Max."

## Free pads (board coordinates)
  round 1.524 hole 1: 0(3.81,7.62) 0(3.81,10.16) 0(3.81,12.7) 0(3.81,15.24) 0(3.81,17.78) 0(3.81,20.32) 0(3.81,22.86) 0(3.81,25.4) 0(3.81,27.94) 0(3.81,30.48) 0(3.81,33.02) 0(3.81,35.56) 0(3.81,38.1) 0(3.81,40.64) 0(3.81,43.18) 0(3.81,45.72) 0(3.81,48.26) 0(3.81,50.8) 1(6.35,22.86) 1(6.35,45.72) 1(6.35,48.26) 1(6.35,50.8) 2(8.89,2.54) 2(8.89,5.08) 2(8.89,7.62) 2(8.89,10.16) 2(8.89,12.7) 2(8.89,15.24) 2(8.89,17.78) 2(8.89,20.32) 2(8.89,22.86) 2(8.89,25.4) 2(8.89,27.94) 2(8.89,30.48) 2(8.89,33.02) 2(8.89,35.56) 2(8.89,38.1) 2(8.89,40.64) 2(8.89,43.18) 2(8.89,45.72) 2(8.89,48.26) 2(8.89,50.8) 3(11.43,2.54) 3(11.43,5.08) 3(11.43,7.62) 3(11.43,10.16) 3(11.43,12.7) 3(11.43,15.24) 3(11.43,17.78) 3(11.43,20.32) 3(11.43,22.86) 3(11.43,25.4) 3(11.43,27.94) 3(11.43,30.48) 3(11.43,33.02) 3(11.43,35.56) 3(11.43,38.1) 3(11.43,40.64) 3(11.43,43.18) 3(11.43,45.72) 3(11.43,48.26) 3(11.43,50.8) 4(13.97,2.54) 4(13.97,5.08) 4(13.97,7.62) 4(13.97,10.16) 4(13.97,12.7) 4(13.97,15.24) 4(13.97,17.78) 4(13.97,20.32) 4(13.97,22.86) 4(13.97,25.4) 4(13.97,27.94) 4(13.97,30.48) 4(13.97,33.02) 4(13.97,35.56) 4(13.97,38.1) 4(13.97,40.64) 4(13.97,43.18) 4(13.97,45.72) 4(13.97,48.26) 4(13.97,50.8) 5(16.51,2.54) 5(16.51,5.08) 5(16.51,7.62) 5(16.51,10.16) 5(16.51,12.7) 5(16.51,15.24) 5(16.51,17.78) 5(16.51,20.32) 5(16.51,22.86) 5(16.51,25.4) 5(16.51,27.94) 5(16.51,30.48) 5(16.51,33.02) 5(16.51,35.56) 5(16.51,38.1) 5(16.51,40.64) 5(16.51,43.18) 5(16.51,45.72) 6(31.5,36.55) 6(34.13,38.156) 6(41.91,2.54) 6(41.91,5.08) 6(41.91,7.62) 6(41.91,10.16) 6(41.91,22.86) 6(41.91,25.4) 6(41.91,27.94) 6(41.91,30.48) 6(41.91,33.02) 6(41.91,35.56) 6(41.91,38.1) 6(41.91,40.64) 6(41.91,43.18) 6(41.91,45.72) 6(41.91,48.26) 6(41.91,50.8) 7(44.45,2.54) 7(44.45,5.08) 7(44.45,7.62) 7(44.45,10.16) 7(44.45,22.86) 7(44.45,25.4) 7(44.45,27.94) 7(44.45,30.48) 7(44.45,33.02) 7(44.45,35.56) 7(44.45,38.1) 7(44.45,40.64) 7(44.45,43.18) 7(44.45,45.72) 7(44.45,48.26) 7(44.45,50.8) 8(46.99,2.54) 8(46.99,5.08) 8(46.99,7.62) 8(46.99,10.16) 8(46.99,12.7) 8(46.99,15.24) 8(46.99,17.78) 8(46.99,20.32) 8(46.99,22.86) 8(46.99,25.4) 8(46.99,27.94) 8(46.99,30.48) 8(46.99,33.02) 8(46.99,35.56) 8(46.99,38.1) 8(46.99,40.64) 8(46.99,43.18) 8(46.99,45.72) 8(46.99,48.26) 8(46.99,50.8) 9(49.53,2.54) 9(49.53,5.08) 9(49.53,7.62) 9(49.53,10.16) 9(49.53,12.7) 9(49.53,15.24) 9(49.53,17.78) 9(49.53,20.32) 9(49.53,22.86) 9(49.53,25.4) 9(49.53,27.94) 9(49.53,30.48) 9(49.53,33.02) 9(49.53,35.56) 9(49.53,38.1) 9(49.53,40.64) 9(49.53,43.18) 9(49.53,45.72) 9(49.53,48.26) 9(49.53,50.8) 10(52.07,2.54) 10(52.07,5.08) 10(52.07,7.62) 10(52.07,10.16) 10(52.07,12.7) 10(52.07,15.24) 10(52.07,17.78) 10(52.07,20.32) 10(52.07,22.86) 10(52.07,25.4) 10(52.07,27.94) 10(52.07,30.48) 10(52.07,33.02) 10(52.07,35.56) 10(52.07,38.1) 10(52.07,40.64) 10(52.07,43.18) 10(52.07,45.72) 10(52.07,48.26) 10(52.07,50.8) 12(57.15,7.62) 12(57.15,10.16) 12(57.15,12.7) 12(57.15,15.24) 12(57.15,17.78) 12(57.15,20.32) 12(57.15,22.86) 12(57.15,25.4) 12(57.15,27.94) 12(57.15,30.48) 12(57.15,33.02) 12(57.15,35.56) 12(57.15,38.1) 12(57.15,40.64) 12(57.15,43.18) 12(57.15,45.72) 12(57.15,48.26) 12(57.15,50.8) ""(39.37,30.48) ""(39.37,33.02)
  round 3.6 hole 2.7 paste-2.6: 666(2.35,2.35) 666(2.35,57.65) 666(57.65,2.35) 666(57.65,57.65)

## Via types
v1: diameter 0.55, hole 0.25, Top Layer to Bottom Layer, 103 vias
v2: diameter 0.55/0.8 (per signal layer), hole 0.25, Top Layer to Bottom Layer, tented top, 22 vias

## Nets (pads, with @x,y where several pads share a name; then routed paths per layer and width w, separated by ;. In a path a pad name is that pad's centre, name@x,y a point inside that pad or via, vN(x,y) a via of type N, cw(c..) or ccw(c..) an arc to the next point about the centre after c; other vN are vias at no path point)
CLK_OUT: R205.2 U101.32 | length 3.5
  Top Layer w0.175: R205.2@31.3,39.7 31.3,40.508 cw(c31.478,40.508) 31.352,40.634 ccw(c30.996,40.99) 31.5,40.99 U101.32@31.5,43.175
D_N: R109.2 U101.3 | length 2.3
  Top Layer w0.15: U101.3@31,50.025 31,51.304 31.35,51.654 R109.2@31.35,52.15
D_P: R110.2 U101.4 | length 2.2
  Top Layer w0.15: R110.2@30.2,52.15 30.2,51.654 30.5,51.354 U101.4@30.5,50.025
GND: C100.2 C101.2 C102.1 C103.2 C104.1 C105.2 C106.1 C107.1 C108.1 C109.2 C110.1 C111.2 C200.1 C201.1 D200.1 J101.2 J101.10 J103.1 J104.5 J200.6@29.16,4.94 J201.7@54.61,44.704 J203.6@6.35,30.48 J203.7@6.35,27.94 pad.0@3.81,27.94 pad.0@3.81,30.48 pad.2@8.89,5.08 pad.3@11.43,5.08 pad.4@13.97,5.08 pad.5@16.51,5.08 pad.6@41.91,5.08 pad.7@44.45,5.08 pad.8@46.99,5.08 pad.9@49.53,5.08 pad.10@52.07,5.08 pad.12@57.15,43.18 pad.666 Q101.2 R111.2 SW200.1 SW200.2 U100.2 U101.5 U101.15 U101.23 U101.35 U101.43 U101.45 U200.3 U200.25 XC100.2 XC100.4 | length 67.2
  Top Layer w0.175: SW200.1@20.125,2.525 SW200.2@20.125,8.025 ; C200.1@20.3,10.3 SW200.2@20.3,8.447 ; v1(22.86,45.312) 23.475,45.312 ; C111.2@23.475,44.775 C110.1@23.475,45.85 ; C109.2@24.775,47.6 U101.15@26.075,47.6 U101.45@27.448,47.6 ; Q101.2@24.985,40.07 24.985,40.994 cw(c26.231,40.994) v1(25.35,41.875) C108.1@26.4,41.875 26.4,42.707 cw(c26.97,42.707) 26.567,43.11 cw(c26.724,42.953) 26.724,43.175 U101.23@27,43.175 27,44.451 cw(c27.175,44.451) U101.45@27.051,44.575 ; C106.1@28.95,53.3 v1(28.95,54.3) ; J200.6@29.15,4.916 cw(c29.184,4.916) J200.6@29.16,4.94 ; U101.5@30,50.025 v1(30,51.075) ; U101.45@31.25,44.625 ccw(c31.31,44.685) 31.31,44.6 U101.35@32.925,44.6 C105.2@34.25,44.6 ; v1(32.675,39.6) 32.675,40.3 J103.1@32.675,40.475 ; U101.43@32.925,48.6 C104.1@34.225,48.6 ; C104.1@34.225,48.475 34.586,48.475 cw(c34.586,47.536) v1(35.25,48.2) ; SW200.2@20.125,8.025 ccw(c19.703,8.447) SW200.2@20.3,8.447 ; SW200.2@20.125,8.025 ccw(c19.703,8.447) SW200.2@20.3,8.447
  Top Layer w0.203: v1(24.228,26.325) C201.1@25.175,26.325 ; v1(26.863,27.226) ccw(c28.012,28.375) 28.012,26.75 U200.3@28.15,26.75 U200.25@29.75,26.75 ; v1(29.092,1.775) D200.1@30.7,1.775
  Top Layer w0.3: pad.0@3.81,27.94 J203.7@6.35,27.94 ; pad.0@3.81,30.48 J203.6@6.35,30.48 ; 19.46,10.3 C200.1@20.3,10.3 ; C102.1@23.4,49.8 23.55,49.65 v1(23.55,48.75) ; v1(25.315,66.711) R111.2@25.315,67.726 ; v1(26.458,66.738) C107.1@26.458,67.776 ; 28.7,68.8 J104.5@28.7,70.7 ; C100.2@29.43,65.746 v1(29.43,66.439) ; U100.2@30.918,63.384 U100.2@30.995,63.384 ; v1(31.85,58.1) 31.85,58.975 C101.2@31.125,59.7 C101.2@31.175,59.75 ; v1(31.85,61.3) 31.85,60.425 C101.2@31.175,59.75 ; C103.2@32.436,63.981 v1(33.326,63.981) ; v1(33.2,59.75) C101.2@31.175,59.75 ; J201.7@54.61,44.704 55.457,44.704 cw(c55.457,44.295) 55.746,44.584 pad.12@57.15,43.18
  Top Layer w0.4: U100.2@30.995,63.384 ccw(c30.995,65.421) C103.2@32.436,63.981
  Top Layer w0.5: v1(19.2,44.3) XC100.4@20.2,44.3 ; v1@36.975,44.725 v1(37,44.725)
  Bottom Layer w0.203: pad.6@41.91,5.08 pad.7@44.45,5.08 pad.8@46.99,5.08 pad.9@49.53,5.08 pad.10@52.07,5.08
  Bottom Layer w0.3: v1@25.287,66.643 ccw(c25.219,66.711) v1(25.315,66.711) ; v1(29.43,66.439) cw(c29.488,66.439) v1@29.447,66.479
  other v1: 18.542,9.796 46.128,21.594 32.272,24.413 40.398,25.327 29.45,25.95 30.55,25.95 29.45,27.05 30.55,27.05 36.203,27.141 40.453,27.847 32.894,29.14 37.311,31.155 28.4,44.4 30.6,44.4 27.3,45.5 29.5,45.5 31.7,45.5 22.7,46.5 28.4,46.6 30.6,46.6 27.3,47.7 29.5,47.7 31.7,47.7 28.4,48.8 30.6,48.8 39.76,49.621 26.478,57.462 27.52,68.045 28.181,68.749
  other v2: 29.65,67.33
NetC100_1: C100.1 U100.4 | length 1.8
  Top Layer w0.175: U100.4@28.33,64.475 ccw(c28.468,64.475) U100.4@28.468,64.337 U100.4@28.8,64.337
  Top Layer w0.3: U100.4@28.33,64.475 v2(28.33,65.11) C100.1@28.33,65.746
NetC106_2: C106.2 U101.6 | length 2.3
  Top Layer w0.175: C106.2@28.95,52.2 28.95,51.808 ccw(c29.633,51.808) 29.15,51.325 cw(c28.305,50.48) 29.5,50.48 U101.6@29.5,50.025
NetD100_1: D100.1 R107.1 | length 3.3
  Top Layer w0.175: v2(29.275,35.446) D100.1@29.275,36.75 29.275,37.233 cw(c31.067,37.233) R107.1@29.8,38.5
  Bottom Layer w0.175: v2@29.225,35.325 ccw(c29.104,35.446) v2(29.275,35.446)
NetD200_2: D200.2 R210.1 | length 1.7
  Top Layer w0.175: D200.2@32.8,1.775 D200.2@33.067,1.508 ; D200.2@33.067,1.508 ccw(c33.238,1.679) 33.238,1.438 33.243,1.432 R210.1@34.417,1.432
  other v2: 33.7,1.45
NetJ101_7: J101.7
NetJ101_8: J101.8
NetJ103_2: J103.2 R108.1 U101.33 | length 3.7
  Top Layer w0.175: U101.33@32,43.175 32.178,43.175 cw(c32.178,42.578) 32.6,43 cw(c32.419,42.819) 32.675,42.819 ; J103.2@32.675,41.825 32.675,42 32.675,42.819 ; R108.1@34.35,42.2 34.118,42.432 ccw(c33.184,41.497) 34.1,42.45 ccw(c33.184,41.497) v2(33.184,42.819) 32.675,42.819
NetJ104_4: J104.4
NetJ106_1: J106.1 XC100.3 | length 2.5
  Top Layer w0.175: XC100.3@20.3,46.5 20.5,46.7 20.5,48.15 J106.1@20.75,48.4 ccw(c21.112,48.038) J106.1@20.6,48.038
NetJ201_8: J201.8@54.61,47.244 pad.12@57.15,45.72 | length 3.2
  Top Layer w0.3: J201.8@54.61,47.244 55.457,47.244 cw(c55.457,46.835) 55.746,47.124 pad.12@57.15,45.72
NetJ203_1: J203.1@6.35,43.18 pad.0@3.81,43.18 | length 2.5
  Top Layer w0.3: pad.0@3.81,43.18 J203.1@6.35,43.18
NetQ100_1: Q100.1 Q101.3 R106.1 | length 4.1
  Top Layer w0.175: R106.1@21.375,37.575 22.825,37.575 cw(c22.825,37.49) v2(22.885,37.55) ; Q100.1@22.885,36.57 v2(22.885,37.55) ; Q101.3@22.885,39.12 v2(22.885,37.55)
NetQ100_3: Q100.3 R104.1 | length 1.7
  Top Layer w0.3: Q100.3@24.985,35.62 25.954,35.62 R104.1@26.502,35.073
NetU101_8: U101.8 | length 2.4
  Top Layer w0.175: v2(27.648,52.167) 27.648,51.977 27.65,51.975 ccw(c28.616,51.975) 27.933,51.292 28.375,50.85 cw(c28.073,50.548) 28.5,50.548 U101.8@28.5,50.025
NetU101_9: U101.9 | length 3.6
  Top Layer w0.175: v2(26.646,53.143) 26.646,52.841 ccw(c28.623,52.841) 26.879,51.909 ccw(c28.623,52.841) 27.225,51.442 27.937,50.73 cw(c27.786,50.579) 28,50.579 U101.9@28,50.025
NetU101_10: U101.10 | length 4.2
  Top Layer w0.175: v2(25.305,53.379) 25.687,52.997 cw(c25.223,52.533) 25.879,52.533 25.879,52.524 ccw(c26.398,52.524) 26.031,52.157 27.419,50.77 cw(c27.217,50.571) 27.5,50.571 U101.10@27.5,50.025
NetU101_11: U101.11 | length 3.2
  Top Layer w0.175: v2(24.852,52.151) ccw(c25.82,52.151) 25.135,51.466 26.452,50.149 ccw(c26.752,50.45) 26.752,50.025 U101.11@27,50.025
NetU101_12: U101.12 | length 0.6
  Top Layer w0.175: U101.12@26.075,49.1 v2(26.075,49.64)
  Bottom Layer w0.175: v2@26.05,49.7 cw(c25.99,49.64) v2(26.075,49.64)
NetU101_18: U101.18 | length 1.4
  Top Layer w0.175: v2@24.9,46.1 24.926,46.074 v2(24.926,46.027) ; U101.18@26.075,46.1 v2@25.102,46.1 ; v2(24.926,46.027) cw(c25.102,45.852) v2@25.102,46.1 ; v2(24.926,46.027) cw(c25.102,45.852) v2@25.102,46.1
NetU101_19: U101.19 | length 3.9
  Top Layer w0.175: v2(23.975,42.875) ccw(c22.703,44.147) 24.502,44.147 cw(c26.203,44.147) 25,45.35 cw(c25.603,44.748) 25.603,45.6 U101.19@26.075,45.6
NetU101_22: U101.22 | length 1
  Top Layer w0.175: v2(25.85,43.125) 25.9,43.175 ccw(c25.478,43.597) 26.075,43.597 U101.22@26.075,44.1
NetU101_25: U101.25 | length 2.6
  Top Layer w0.175: U101.25@28,43.175 28,42.809 ccw(c28.568,42.809) 28.166,42.407 cw(c27.778,42.019) 28.327,42.019 v2(28.327,40.686)
NetU101_26: U101.26
NetU101_27: U101.27 | length 0.9
  Top Layer w0.175: v2@28.898,42.264 ccw(c28.653,42.509) 28.988,42.417 ccw(c28.653,42.509) v2@29,42.509 ; v2@29,42.53 U101.27@29,43.175
  other v2: 28.948,42.264
NetU101_29: U101.29 | length 2.1
  Top Layer w0.175: v2(29.88,41.079) 29.88,41.395 cw(c30.066,41.395) 29.934,41.526 ccw(c29.776,41.685) 30,41.685 U101.29@30,43.175
NetU101_40: U101.40
NetU101_41: U101.41
PA0: J201.2@54.61,32.004 pad.12@57.15,30.48 R200.2 | length 23.6
  Top Layer w0.2: R200.2@35.529,33.964 38.093,33.964 ccw(c38.093,34.546) 38.505,34.135 cw(c38.959,33.68) 38.959,34.323 52.671,34.323 cw(c52.671,33.799) 53.041,34.17 cw(c52.441,33.569) 53.29,33.569 ccw(c53.882,33.569) 53.463,33.151 J201.2@54.61,32.004
  Top Layer w0.3: J201.2@54.61,32.004 55.457,32.004 cw(c55.457,31.595) 55.746,31.884 pad.12@57.15,30.48
PA0_RST_PDI: pad.6@34.13,38.156 R200.1 R201.1 R203.2 U200.23 | length 27.4
  Top Layer w0.2: U200.23@29.25,28.36 29.25,29.697 cw(c30.82,29.697) 29.71,30.807 32.779,33.877 ccw(c32.684,33.972) R201.1@32.819,33.972 ; R200.1@34.303,33.972 R201.1@32.819,33.972 ; R203.2@36.758,50.008 37.6,49.165 ; 37.749,49.016 37.602,49.164 ; R201.1@32.819,33.972 33.386,34.539 ccw(c31.59,36.335) 34.13,36.335 pad.6@34.13,38.156 37.6,41.627 ccw(c35.445,43.782) 37.602,41.628 ccw(c35.445,43.782) 38.493,43.782 38.493,47.01 ccw(c35.445,47.01) 37.602,49.164 ; 37.602,49.164 ccw(c35.445,47.01) 37.6,49.165 ; 37.602,49.164 37.6,49.165
PA1_I2C_SDA: J201.9@54.61,49.784 pad.12@57.15,48.26 U200.24 | length 46.6
  Top Layer w0.2: U200.24@28.75,28.36 v1(28.75,30.773)
  Top Layer w0.3: J201.9@54.61,49.784 55.457,49.784 cw(c55.457,49.375) 55.746,49.664 pad.12@57.15,48.26
  Bottom Layer w0.2: v1(28.75,30.773) 28.75,31.718 cw(c29.65,31.718) 29.014,32.354 cw(c29.611,31.757) 29.181,32.484 cw(c29.611,31.757) 29.611,32.602 34.77,32.602 ccw(c34.77,35.142) 36.566,33.346 38.856,35.636 ccw(c37.06,37.432) 39.6,37.432 39.6,47.268 cw(c42.14,47.268) 40.344,49.064 cw(c42.083,47.324) 42.083,49.784 J201.9@54.61,49.784
PA2_I2C_SCL: J201.10@54.61,52.324 pad.12@57.15,50.8 U200.1 | length 50.1
  Top Layer w0.2: v1(27.868,30.599) cw(c27.21,29.942) 28.14,29.942 U200.1@28.14,27.75
  Top Layer w0.3: J201.10@54.61,52.324 55.457,52.324 cw(c55.457,51.915) 55.746,52.204 pad.12@57.15,50.8
  Bottom Layer w0.2: v1(27.868,30.599) 27.868,31.222 cw(c29.773,31.222) 28.426,32.569 cw(c29.993,31.002) 29.993,33.219 34.431,33.219 ccw(c34.431,35.759) 36.227,33.962 38.276,36.011 ccw(c36.48,37.807) 39.02,37.807 39.02,49.555 cw(c41.56,49.555) 39.764,51.351 39.993,51.58 cw(c41.789,49.784) 41.789,52.324 J201.10@54.61,52.324
PA3_CLKI: pad.6@31.5,36.55 R202.1 R205.1 U200.2 | length 13.8
  Top Layer w0.2: U200.2@28.14,27.25 cw(c28.14,27.931) 27.658,27.45 27.427,27.681 cw(c29.162,29.416) 26.708,29.416 26.708,30.155 cw(c29.248,30.155) 27.452,31.951 R202.1@28.479,32.978 28.479,33.31 cw(c29.147,33.31) 28.675,33.782 31.401,36.509 cw(c31.5,36.41) pad.6@31.5,36.55 31.5,37.384 ccw(c31.075,37.384) 31.375,37.685 cw(c31.557,37.867) 31.3,37.867 R205.1@31.3,38.5
PA3_PWM_W3: J202.5 pad.12@57.15,17.78 R202.2 | length 41.9
  Top Layer w0.2: v1(29.679,31.776) R202.2@29.679,32.978
  Top Layer w0.3: J202.5@54.61,17.78 pad.12@57.15,17.78
  Bottom Layer w0.2: v1@29.663,31.737 ccw(c29.624,31.776) v1(29.679,31.776) ; v1@29.679,31.779 34.585,31.779 cw(c34.585,30.004) 35.841,31.259 37.3,29.8 ccw(c38.101,30.601) 38.101,29.468 51.966,29.468 cw(c51.966,27.15) 53.605,28.789 54.391,28.003 ccw(c55.229,28.841) 55.229,27.656 cw(c55.229,26.868) 55.786,27.426 cw(c54.923,26.562) 56.048,27.037 cw(c54.206,26.485) 56.129,26.485 56.129,19.504 cw(c54.382,19.504) 55.617,18.269 55.494,18.146 cw(c54.61,19.031) J202.5@54.61,17.78
PA4_AIN04: J204.1@6.35,20.32 pad.0@3.81,20.32 U200.5 | length 40.9
  Top Layer w0.2: J204.1@6.35,20.32 J204.1@7.036,21.006 ; v1(22.579,27.342) ccw(c24.142,27.342) 23.037,26.237 ccw(c24.213,27.414) 23.038,26.236 ccw(c24.213,27.414) 24.213,25.75 U200.5@28.15,25.75
  Top Layer w0.3: pad.0@3.81,20.32 J204.1@6.35,20.32
  Bottom Layer w0.2: J204.1@6.35,20.32 cw(c6.35,21.692) 4.978,21.692 4.978,30.403 cw(c6.433,30.403) 5.404,31.432 cw(c6.23,30.606) 6.23,31.774 16.759,31.774 cw(c16.759,28.421) 19.129,30.792 v1(22.579,27.342)
PA5_AIN05: J204.2@6.35,17.78 pad.0@3.81,17.78 U200.6 | length 37.4
  Top Layer w0.2: J204.2@6.35,17.78 J204.2@7.036,18.466 ; v1(21.908,26.653) 22.711,25.85 ccw(c24.159,27.298) 24.159,25.25 U200.6@28.14,25.25
  Top Layer w0.3: pad.0@3.81,17.78 J204.2@6.35,17.78
  Bottom Layer w0.2: J204.2@6.35,17.78 6.763,18.193 ccw(c4.967,19.989) 7.507,19.989 7.507,28.753 cw(c8.175,28.753) 7.702,29.225 cw(c8.082,28.846) 8.082,29.382 18.257,29.382 cw(c18.257,27.158) 19.83,28.731 v1(21.908,26.653)
PA6_AIN06: J204.3@6.35,15.24 pad.0@3.81,15.24 R213.2 U200.7 | length 42.3
  Top Layer w0.2: J204.3@6.35,15.24 J204.3@7.036,15.926 ; R213.2@24.275,23.368 24.28,23.373 v1(24.28,24.64) U200.7@28.75,24.64
  Top Layer w0.3: pad.0@3.81,15.24 J204.3@6.35,15.24
  Bottom Layer w0.2: J204.3@6.35,15.24 7.113,16.003 ccw(c5.317,17.799) 7.857,17.799 7.857,28.119 cw(c8.745,28.119) 8.117,28.747 cw(c8.806,28.059) 8.806,29.032 17.979,29.032 cw(c17.979,26.873) 19.506,28.4 cw(c18.707,27.601) 19.837,27.601 19.837,26.949 ccw(c21.957,26.949) 20.458,25.45 20.707,25.201 ccw(c22.06,26.554) 22.06,24.64 v1(24.28,24.64)
PA6_PTC2: CS200.1 R213.1 | length 2.7
  Top Layer w0.2: R213.1@24.275,22.368 24.275,19.663 v1(24.281,19.658)
PA7_AIN07: J204.4@6.35,12.7 pad.0@3.81,12.7 R214.2 U200.8 | length 40.4
  Top Layer w0.2: J204.4@6.35,12.7 J204.4@7.036,13.386 ; R214.2@25.675,23.368 cw(c26.379,22.665) 26.379,23.66 v1(26.693,23.66) 28.767,23.66 ccw(c28.767,24.187) 29.14,23.814 ccw(c28.875,24.08) 29.25,24.08 U200.8@29.25,24.64
  Top Layer w0.3: pad.0@3.81,12.7 J204.4@6.35,12.7
  Bottom Layer w0.2: 6.954,13.304 cw(c8.683,11.576) 8.683,14.02 8.831,14.02 ccw(c8.831,15.203) 10.014,15.203 10.014,25.204 cw(c11.285,25.204) 10.386,26.103 cw(c11.929,24.56) 11.929,26.742 16.704,26.742 cw(c16.704,24.202) 18.5,25.998 20.095,24.404 ccw(c21.891,26.2) 21.891,23.66 v1(26.693,23.66)
PA7_PTC3: CS201.1 R214.1 | length 9.5
  Top Layer w0.2: R214.1@25.675,22.368 25.675,21.671 v1(25.683,21.663)
  Bottom Layer w0.2: v1(25.683,21.663) cw(c26.492,20.854) 26.492,21.999 30.793,21.999 cw(c30.793,20.5) 31.853,21.56 v1(33.575,19.838)
PB0_AIN11: J204.6@6.35,7.62 pad.0@3.81,7.62 U200.16 | length 50.2
  Top Layer w0.2: U200.16@31.86,26.75 32.4,26.75 ccw(c32.4,27.165) 32.693,26.872 cw(c33.439,26.126) 33.211,27.155 cw(c33.439,26.126) 33.439,27.18 v1(33.511,27.18)
  Top Layer w0.3: pad.0@3.81,7.62 J204.6@6.35,7.62
  Bottom Layer w0.2: J204.6@6.35,7.62 ccw(c6.35,7.823) 6.493,7.679 7.075,8.261 cw(c8.68,6.655) 8.68,8.925 11.687,8.925 ccw(c11.687,9.832) 12.351,9.215 ccw(c11.687,9.832) 12.593,9.832 12.593,22.966 cw(c13.425,22.966) 12.837,23.553 cw(c13.676,22.714) 13.676,23.901 18.3,23.901 cw(c18.3,22.746) 19.117,23.563 19.388,23.292 ccw(c21.184,25.088) 21.184,22.548 29.928,22.548 ; 29.928,22.549 30.963,22.549 ccw(c30.899,25.088) 32.695,23.292 33.112,23.709 ccw(c31.316,25.505) 33.856,25.505 33.856,26.714 ccw(c33.565,26.714) 33.771,26.92 v1(33.511,27.18)
PB1_AIN10: J204.5@6.35,10.16 pad.0@3.81,10.16 U200.15 | length 47
  Top Layer w0.2: J204.5@6.35,10.16 J204.5@7.036,10.846 ; U200.15@31.86,26.25 32.7,26.25 ccw(c32.7,27.136) 33.327,26.509 v1(33.327,26.493)
  Top Layer w0.3: pad.0@3.81,10.16 J204.5@6.35,10.16
  Bottom Layer w0.2: J204.5@6.35,10.16 6.748,10.558 cw(c8.544,8.762) 8.544,11.302 8.825,11.302 ccw(c8.825,12.84) 10.364,12.84 10.364,22.941 cw(c11.889,22.941) 10.81,24.02 cw(c11.462,23.368) 11.462,24.29 18.309,24.29 cw(c18.309,22.183) 19.799,23.673 ccw(c21.413,25.287) 21.413,23.004 30.829,23.004 ccw(c30.829,25.544) 32.625,23.748 32.87,23.993 ccw(c31.767,25.096) 33.327,25.096 v1(33.327,26.493)
PB2_UART_TX: J202.2 pad.12@57.15,10.16 R206.2 U200.14 | length 66.1
  Top Layer w0.175: R206.2@19.625,39.95 19.625,34.077 ccw(c21.606,34.077) 21.577,32.096 ccw(c21.606,34.077) 21.606,32.096
  Top Layer w0.2: U200.14@31.86,25.75 34.041,25.75 cw(c34.041,23.769) 35.442,25.17 v1(35.456,25.155) ; J202.2@54.114,10.656 J202.2@54.61,10.16
  Top Layer w0.3: J202.2@54.61,10.16 pad.12@57.15,10.16
  Bottom Layer w0.175: v1(21.908,32.096) 24.135,32.096 cw(c24.135,30.136) 26.094,30.136 ccw(c27.661,30.136) 27.098,28.674
  Bottom Layer w0.2: 27.098,28.674 ccw(c27.734,30.55) 27.734,28.569 33.777,28.569 cw(c33.777,27.133) 34.793,28.148 cw(c33.191,26.547) 35.456,26.547 v1(35.456,25.155) 35.754,24.857 ccw(c37.155,26.258) 37.155,24.277 49.998,24.277 cw(c49.998,23.263) 51.013,23.263 51.013,12.249 ccw(c51.961,12.249) 51.961,11.301 52.417,11.301 cw(c52.417,8.761) 54.213,10.557 J202.2@54.61,10.16
PB3_UART_RX: J202.1 pad.12@57.15,7.62 R207.2 U200.13 | length 68.6
  Top Layer w0.2: R207.2@20.875,40.7 20.875,39.795 cw(c19.68,39.795) 20.525,38.95 ccw(c21.672,37.803) 20.05,37.803 20.05,35.279 ccw(c22.59,35.279) 20.794,33.483 v1(21.072,33.204) ; U200.13@31.86,25.25 33.787,25.25 cw(c33.787,23.911) v1(34.734,24.858) ; J202.1@54.279,7.951 J202.1@54.61,7.62
  Top Layer w0.3: J202.1@54.61,7.62 pad.12@57.15,7.62
  Bottom Layer w0.2: v1(21.072,33.204) cw(c21.072,33.25) 21.026,33.25 cw(c21.026,33.19) 21.086,33.19 21.086,32.096 ccw(c21.611,32.096) 21.611,31.571 24.135,31.571 cw(c24.135,30.067) 25.639,30.067 ccw(c27.513,30.067) 27.513,28.193 33.701,28.193 cw(c33.701,27.186) 34.412,27.898 cw(c33.635,27.121) 34.734,27.121 v1(34.734,24.858) 35.085,24.507 ccw(c36.486,25.908) 36.486,23.927 49.853,23.927 cw(c49.853,23.202) 50.578,23.202 50.578,10.6 ccw(c52.349,10.6) 52.349,8.829 cw(c52.349,6.289) 54.145,8.085 J202.1@54.61,7.62
PB4_PWM_W1: J202.3 pad.12@57.15,12.7 U200.12 | length 41.4
  Top Layer w0.2: U200.12@31.25,24.64 31.25,24.026 ccw(c31.605,24.026) 31.605,23.671 34.349,23.671 ccw(c34.349,26.234) 36.161,24.422 36.22,24.481 ccw(c34.603,26.098) 36.356,24.629 ccw(c34.603,26.098) v1(36.89,26.098) ; J202.3@54.114,13.196 J202.3@54.61,12.7
  Top Layer w0.3: J202.3@54.61,12.7 pad.12@57.15,12.7
  Bottom Layer w0.2: v1(36.89,26.098) 37.718,26.098 ccw(c37.718,26.8) 37.96,26.142 ccw(c37.718,26.8) 38.214,26.304 cw(c38.63,25.887) 38.63,26.476 52.436,26.476 cw(c52.436,25.802) 53.11,25.802 53.11,15.021 ccw(c55.091,15.021) 53.69,13.62 J202.3@54.61,12.7
PB5_PWM_W2: J202.4 pad.12@57.15,15.24 U200.11 | length 41.1
  Top Layer w0.2: U200.11@30.75,24.64 30.75,23.951 ccw(c31.487,23.951) 31.487,23.215 34.339,23.215 ccw(c34.339,26.263) 36.494,24.108 36.716,24.329 ccw(c34.561,26.485) 37.609,26.485 v1(37.609,26.864) ; J202.4@54.114,15.736 J202.4@54.61,15.24
  Top Layer w0.3: J202.4@54.61,15.24 pad.12@57.15,15.24
  Bottom Layer w0.2: v1(37.609,26.864) cw(c37.772,26.864) v1@37.61,26.882 ; v1@37.657,26.979 ccw(c37.772,26.864) v1@37.61,26.882 ; J202.4@54.61,15.24 54.06,15.79 cw(c55.461,17.19) 53.48,17.19 53.48,26.012 ccw(c52.611,26.012) 52.611,26.882 v1@37.61,26.882
PB6: J202.7 pad.12@57.15,22.86 U200.10 | length 38.8
  Top Layer w0.2: U200.10@30.25,24.64 30.25,23.601 ccw(c30.987,23.601) 30.987,22.865 37.315,22.865 ccw(c37.315,24.522) 38.487,23.35 ccw(c37.301,24.536) 38.978,24.536 38.978,24.931 cw(c40.747,24.931) 39.496,26.183 cw(c40.418,25.261) 40.418,26.565 56.931,26.565 cw(c56.931,24.541) 58.362,25.972 cw(c57.535,25.145) 58.705,25.145 cw(c56.941,25.145) 58.188,23.898 pad.12@57.15,22.86 ; J202.7@54.279,23.191 J202.7@54.61,22.86
  Top Layer w0.3: J202.7@54.61,22.86 pad.12@57.15,22.86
